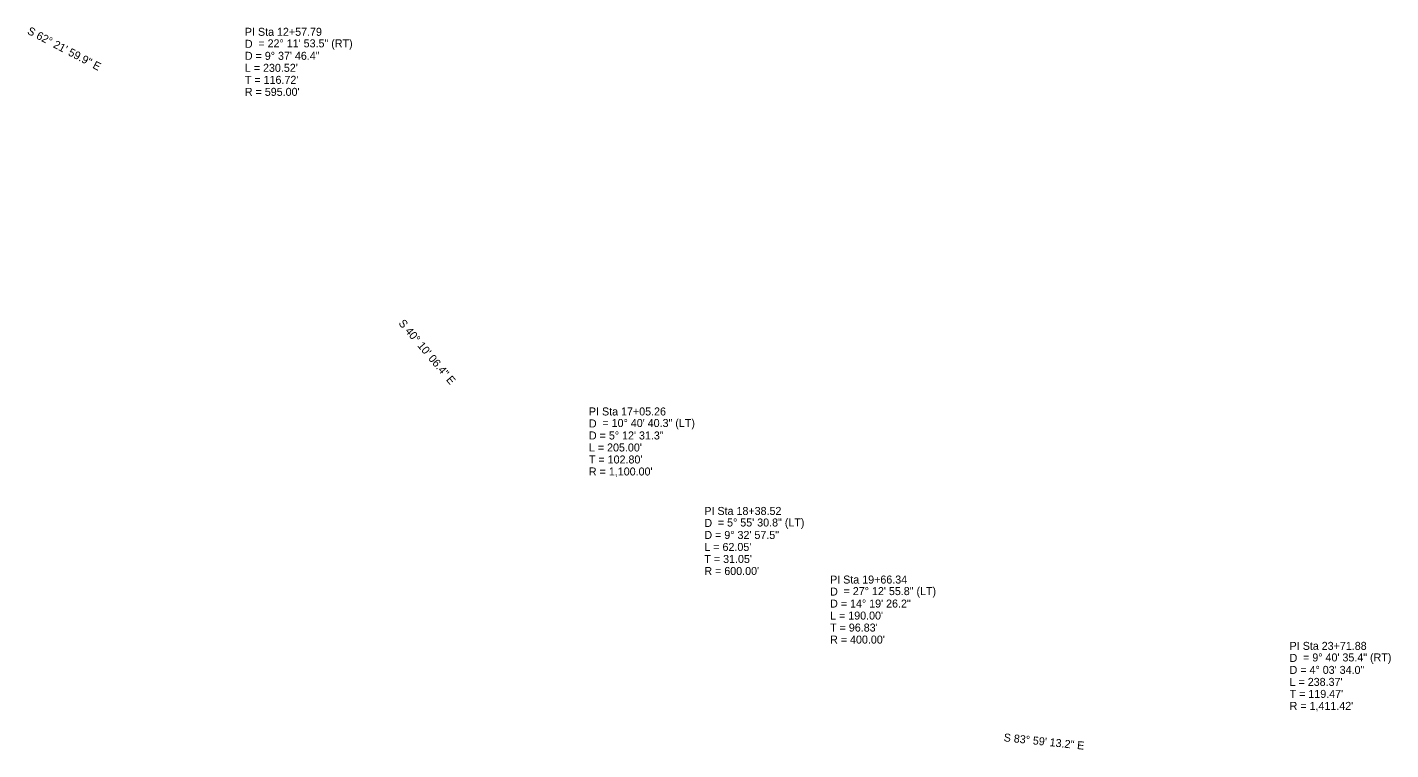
# Model space of a CAD drawing. Extents: x 928111 to 937215, y 684185 to 686530.
# Drawn here: x 928111 to 929303, y 685899 to 686530 of the extents above; entities that cross this region are included whole.
import ezdxf

# ---------------------------------------------------------------- set-up
doc = ezdxf.new("R2010")
doc.units = 0
doc.layers.add('Exist Horizontal Alignment Curve and Spiral Data', color=7, linetype='Continuous')
doc.layers.add('Exist Horizontal Alignment Direction Label', color=7, linetype='Continuous')

msp = doc.modelspace()

# ---------------------------------------------------------------- texts
at = {"layer": 'Exist Horizontal Alignment Curve and Spiral Data'}
for s, p in [('PI Sta 12+57.79', (928301, 686523)), ('D', (928301, 686512.5)), ('= 22%%d 11\' 53.5" (RT)', (928312.8, 686512.9)), ('D = 9%%d 37\' 46.4"', (928301, 686502)), ("L = 230.52'", (928301, 686491.5)), ("T = 116.72'", (928301, 686481)), ("R = 595.00'", (928301, 686470.5)), ('PI Sta 17+05.26', (928602, 686191)), ('D', (928602, 686180.5)), ('= 10%%d 40\' 40.3" (LT)', (928613.8, 686180.9)), ('D = 5%%d 12\' 31.3"', (928602, 686170)), ("L = 205.00'", (928602, 686159.5)), ("T = 102.80'", (928602, 686149)), ("R = 1,100.00'", (928602, 686138.5)), ('PI Sta 18+38.52', (928703, 686104)), ('D', (928703, 686093.5)), ('= 5%%d 55\' 30.8" (LT)', (928714.8, 686093.9)), ('D = 9%%d 32\' 57.5"', (928703, 686083)), ("L = 62.05'", (928703, 686072.5)), ("T = 31.05'", (928703, 686062)), ("R = 600.00'", (928703, 686051.5)), ('PI Sta 19+66.34', (928813, 686044)), ('D', (928813, 686033.5)), ('= 27%%d 12\' 55.8" (LT)', (928824.8, 686033.9)), ('D = 14%%d 19\' 26.2"', (928813, 686023)), ("L = 190.00'", (928813, 686012.5)), ("T = 96.83'", (928813, 686002)), ("R = 400.00'", (928813, 685991.5)), ('PI Sta 23+71.88', (929215, 685986)), ('D', (929215, 685975.5)), ('= 9%%d 40\' 35.4" (RT)', (929226.8, 685975.9)), ('D = 4%%d 03\' 34.0"', (929215, 685965)), ("L = 238.37'", (929215, 685954.5)), ("T = 119.47'", (929215, 685944)), ("R = 1,411.42'", (929215, 685933.5))]:
    msp.add_text(s, height=7, dxfattribs=at).set_placement(p)
at = {"layer": 'Exist Horizontal Alignment Direction Label'}
for s, rotation, p in [('S 62%%d 21\' 59.9" E', 332.3666, (928110, 686525.1)), ('S 40%%d 10\' 06.4" E', 310.1684, (928435, 686271.4)), ('S 83%%d 59\' 13.2" E', 353.987, (928964.6, 685906.1))]:
    msp.add_text(s, height=7, rotation=rotation, dxfattribs=at).set_placement(p)

doc.saveas('drawing.dxf')
